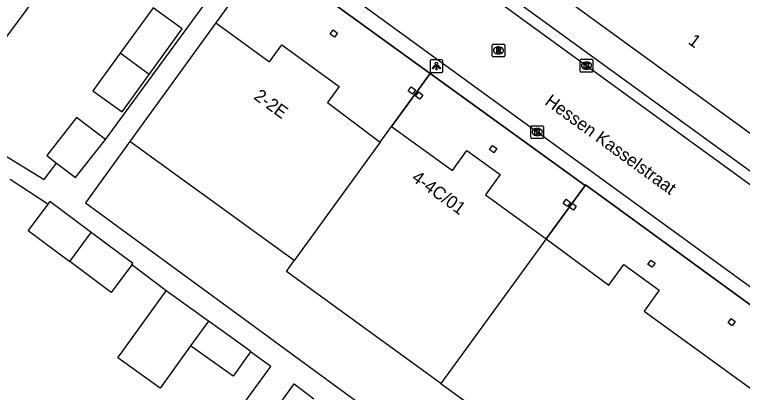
# Model space of a CAD drawing. Extents: x 160107 to 160928, y 382056 to 382918.
# Drawn here: x 160406.9 to 160464.1, y 382376.5 to 382406.2 of the extents above; entities that cross this region are included whole.
import ezdxf

# ---------------------------------------------------------------- set-up
doc = ezdxf.new("R2010")
doc.units = 0
for name, color, linetype in [('IMGEO_Kolk', 7, 'Continuous'), ('IMGEO_Lichtpunt', 7, 'Continuous'), ('IMGEO_Openbare_ruimte_label', 7, 'Continuous'), ('IMGEO_Pand', 7, 'Continuous'), ('IMGEO_Pand_nummerreeks', 7, 'Continuous'), ('IMGEO_Pand_overbouw', 7, 'Continuous'), ('IMGEO_Rijbaan_lokaal_open', 7, 'Continuous'), ('IMGEO_Rioolput', 7, 'Continuous'), ('IMGEO_Voetpad_open', 7, 'Continuous')]:
    doc.layers.add(name, color=color, linetype=linetype)

msp = doc.modelspace()

# ---------------------------------------------------------------- linework, layer by layer
at = {"layer": 'IMGEO_Kolk'}
for p, q in [((160451.322, 382401.736), (160451.322, 382402.588)), ((160451.397, 382402.662), (160452.249, 382402.662)), ((160451.81, 382402.442), (160451.835, 382402.442)), ((160452.323, 382402.588), (160452.323, 382401.736)), ((160451.833, 382401.882), (160451.808, 382401.882)), ((160452.249, 382401.662), (160451.397, 382401.662)), ((160447.445, 382396.513), (160447.445, 382397.365)), ((160447.52, 382397.439), (160448.372, 382397.439)), ((160447.933, 382397.219), (160447.958, 382397.219)), ((160448.446, 382397.365), (160448.446, 382396.513)), ((160447.956, 382396.659), (160447.931, 382396.659)), ((160448.372, 382396.439), (160447.52, 382396.439))]:
    msp.add_line(p, q, dxfattribs=at)
for points in [[(160451.322, 382401.736), (160451.322, 382402.588)], [(160451.397, 382402.662), (160452.249, 382402.662)], [(160451.643, 382402.362), (160451.766, 382402.362), (160451.766, 382402.211), (160451.896, 382402.362), (160452.06, 382402.362), (160451.914, 382402.211), (160452.067, 382401.962), (160451.915, 382401.962), (160451.83, 382402.126), (160451.766, 382402.059), (160451.766, 382401.962), (160451.643, 382401.962), (160451.643, 382402.362)], [(160452.323, 382402.588), (160452.323, 382401.736)], [(160452.249, 382401.662), (160451.397, 382401.662)], [(160447.445, 382396.513), (160447.445, 382397.365)], [(160447.52, 382397.439), (160448.372, 382397.439)], [(160448.446, 382397.365), (160448.446, 382396.513)], [(160447.766, 382397.139), (160447.889, 382397.139), (160447.889, 382396.988), (160448.019, 382397.139), (160448.183, 382397.139), (160448.037, 382396.988), (160448.19, 382396.739), (160448.038, 382396.739), (160447.953, 382396.903), (160447.889, 382396.836), (160447.889, 382396.739), (160447.766, 382396.739), (160447.766, 382397.139)], [(160448.372, 382396.439), (160447.52, 382396.439)]]:
    msp.add_lwpolyline(points, dxfattribs=at)
for centre, start, end in [((160451.399, 382402.586), 91.552, 178.448), ((160451.399, 382402.586), 91.552, 178.448), ((160452.247, 382402.586), 1.552, 88.448), ((160452.247, 382402.586), 1.552, 88.448), ((160451.399, 382401.738), 181.552, 268.448), ((160451.399, 382401.738), 181.552, 268.448), ((160452.247, 382401.738), 271.552, 358.448), ((160452.247, 382401.738), 271.552, 358.448), ((160447.522, 382397.363), 91.552, 178.448), ((160447.522, 382397.363), 91.552, 178.448), ((160448.37, 382397.363), 1.552, 88.448), ((160448.37, 382397.363), 1.552, 88.448), ((160447.522, 382396.515), 181.552, 268.448), ((160447.522, 382396.515), 181.552, 268.448), ((160448.37, 382396.515), 271.552, 358.448), ((160448.37, 382396.515), 271.552, 358.448)]:
    msp.add_arc(centre, 0.0765, start, end, dxfattribs=at)
for centre, major_axis, ratio, start_param, end_param in [((160451.809, 382402.162), (-0.387, 0.002), 0.722429, 4.712389, 7.853982), ((160451.834, 382402.162), (-0.39, 0.002), 0.717154, 1.570796, 4.712389), ((160447.932, 382396.939), (-0.387, 0.002), 0.722429, 4.712389, 7.853982), ((160447.957, 382396.939), (-0.39, 0.002), 0.717154, 1.570796, 4.712389)]:
    msp.add_ellipse(centre, major_axis=major_axis, ratio=ratio, start_param=start_param, end_param=end_param, dxfattribs=at)
at = {"layer": 'IMGEO_Lichtpunt'}
for p, q in [((160439.517, 382402.537), (160439.517, 382401.73)), ((160439.517, 382402.537), (160439.517, 382401.73)), ((160440.419, 382402.632), (160439.611, 382402.632)), ((160440.419, 382402.632), (160439.611, 382402.632)), ((160440.513, 382401.73), (160440.513, 382402.537)), ((160440.513, 382401.73), (160440.513, 382402.537)), ((160439.611, 382401.636), (160440.419, 382401.636)), ((160439.611, 382401.636), (160440.419, 382401.636))]:
    msp.add_line(p, q, dxfattribs=at)
for points in [[(160439.891, 382402.201), (160439.93, 382402.173), (160439.742, 382401.911), (160439.704, 382401.938), (160439.891, 382402.201)], [(160439.993, 382402.153), (160440.04, 382402.153), (160440.04, 382401.831), (160439.993, 382401.831), (160439.993, 382402.153)], [(160440.103, 382402.173), (160440.141, 382402.2), (160440.328, 382401.938), (160440.289, 382401.91), (160440.103, 382402.173)]]:
    msp.add_lwpolyline(points, dxfattribs=at)
msp.add_circle((160440.016, 382402.335), 0.0994, dxfattribs=at)
for centre, start, end in [((160439.611, 382402.537), 90, 180), ((160439.611, 382402.537), 90, 180), ((160440.419, 382402.537), 0, 90), ((160440.419, 382402.537), 0, 90), ((160439.611, 382401.73), 180, 270), ((160439.611, 382401.73), 180, 270), ((160440.419, 382401.73), 270, 0), ((160440.419, 382401.73), 270, 360)]:
    msp.add_arc(centre, 0.0946, start, end, dxfattribs=at)
at = {"layer": 'IMGEO_Pand'}
for points in [[(160496.01, 382423.19), (160472.739, 382390.992), (160443.139, 382412.509), (160443.937, 382413.611), (160446.425, 382417.048), (160445.872, 382417.448), (160446.399, 382418.176), (160446.953, 382417.775), (160449.135, 382420.786), (160468.398, 382406.625), (160478.135, 382420.019), (160485.824, 382430.595)], [(160407.012, 382409.239), (160408.78, 382407.934), (160405.026, 382402.846), (160403.258, 382404.151)], [(160417.428, 382401.465), (160420.031, 382405.061), (160417.747, 382406.714), (160415.168, 382403.151)], [(160422.678, 382405.539), (160415.913, 382396.21)], [(160422.678, 382405.539), (160426.902, 382402.469), (160427.869, 382403.803), (160432.376, 382400.519), (160431.463, 382399.257), (160435.599, 382396.137)], [(160432.001, 382404.403), (160431.668, 382404.65), (160431.909, 382404.97), (160432.241, 382404.723), (160432.001, 382404.403)], [(160415.168, 382403.151), (160413.017, 382400.18), (160415.301, 382398.527), (160417.428, 382401.465)], [(160417.428, 382401.465), (160415.168, 382403.151)], [(160438.144, 382399.928), (160437.809, 382400.172), (160438.046, 382400.494), (160438.383, 382400.254), (160438.144, 382399.928)], [(160438.721, 382399.517), (160438.379, 382399.769), (160438.626, 382400.094), (160438.961, 382399.849), (160438.721, 382399.517)], [(160413.99, 382396.362), (160411.724, 382398.098), (160409.383, 382395.092), (160410.161, 382394.496)], [(160435.599, 382396.137), (160436.5, 382397.379), (160441.294, 382393.92), (160442.415, 382395.503), (160445.027, 382393.592), (160443.871, 382392.002), (160448.643, 382388.532)], [(160410.161, 382394.496), (160411.65, 382393.356), (160413.99, 382396.362)], [(160428.847, 382386.83), (160415.913, 382396.21)], [(160435.599, 382396.137), (160428.847, 382386.83)], [(160444.525, 382395.318), (160444.188, 382395.56), (160444.425, 382395.886), (160444.761, 382395.641), (160444.525, 382395.318)], [(160412.884, 382389.036), (160409.619, 382391.476), (160409.471, 382391.278)], [(160449.995, 382391.327), (160450.23, 382391.653), (160450.566, 382391.409), (160450.328, 382391.08), (160449.995, 382391.327)], [(160409.471, 382391.278), (160407.922, 382389.206), (160411.187, 382386.765)], [(160450.785, 382390.791), (160450.459, 382391.022), (160450.691, 382391.351), (160451.018, 382391.12), (160450.785, 382390.791)], [(160411.187, 382386.765), (160412.884, 382389.036)], [(160416.073, 382386.493), (160416.149, 382386.595), (160412.884, 382389.036)], [(160448.643, 382388.532), (160440.354, 382377.176)], [(160448.643, 382388.532), (160453.568, 382384.905), (160454.761, 382386.535), (160457.54, 382384.501), (160456.351, 382382.868), (160466.187, 382375.719), (160467.365, 382377.35), (160470.157, 382375.333), (160468.968, 382373.7), (160478.776, 382366.565), (160479.978, 382368.175), (160482.771, 382366.161), (160481.591, 382364.526), (160491.395, 382357.376), (160492.59, 382358.99), (160495.379, 382356.975), (160494.187, 382355.357), (160499.315, 382351.619)], [(160416.073, 382386.493), (160414.452, 382384.325), (160411.187, 382386.765)], [(160440.354, 382377.176), (160428.236, 382385.988), (160428.847, 382386.83)], [(160456.977, 382386.304), (160456.652, 382386.537), (160456.888, 382386.865), (160457.212, 382386.632), (160456.977, 382386.304)], [(160420.696, 382380.133), (160418.302, 382376.803), (160414.982, 382379.19), (160418.775, 382384.467)], [(160422.096, 382382.08), (160418.775, 382384.467)], [(160422.096, 382382.08), (160420.696, 382380.133)], [(160425.404, 382379.653), (160425.427, 382379.685), (160422.448, 382381.827), (160422.096, 382382.08)], [(160463.191, 382382.273), (160463.516, 382382.04), (160463.282, 382381.713), (160462.957, 382381.946), (160463.191, 382382.273)], [(160425.404, 382379.653), (160424.028, 382377.738), (160420.696, 382380.133)], [(160440.354, 382377.176), (160491.079, 382340.291), (160491.222, 382340.488), (160491.833, 382341.328)]]:
    msp.add_lwpolyline(points, dxfattribs=at)
at = {"layer": 'IMGEO_Pand_overbouw'}
for points in [[(160435.599, 382396.137), (160436.5, 382397.379), (160439.531, 382401.558), (160426.593, 382410.937), (160422.678, 382405.539), (160426.902, 382402.469), (160427.869, 382403.803), (160432.376, 382400.519), (160431.463, 382399.257)], [(160439.531, 382401.558), (160436.5, 382397.379), (160441.294, 382393.92), (160442.415, 382395.503), (160445.027, 382393.592), (160443.871, 382392.002), (160448.643, 382388.532), (160451.707, 382392.731)], [(160451.707, 382392.731), (160448.643, 382388.532), (160453.568, 382384.905), (160454.761, 382386.535), (160457.54, 382384.501), (160456.351, 382382.868), (160466.187, 382375.719), (160467.365, 382377.35), (160470.157, 382375.333), (160468.968, 382373.7), (160478.776, 382366.565), (160479.978, 382368.175), (160482.771, 382366.161), (160481.591, 382364.526), (160491.395, 382357.376), (160492.59, 382358.99), (160495.379, 382356.975), (160494.187, 382355.357), (160499.315, 382351.619), (160502.419, 382355.889), (160498.105, 382359.029), (160451.741, 382392.778)]]:
    msp.add_lwpolyline(points, close=True, dxfattribs=at)
at = {"layer": 'IMGEO_Rijbaan_lokaal_open'}
for points in [[(160498.608, 382368.158), (160429.934, 382418.064), (160429.691, 382417.738), (160411.998, 382430.553)], [(160498.881, 382360.163), (160498.767, 382359.996), (160408.261, 382425.803)]]:
    msp.add_lwpolyline(points, dxfattribs=at)
at = {"layer": 'IMGEO_Rioolput'}
for p, q in [((160444.399, 382402.934), (160444.399, 382403.786)), ((160444.474, 382403.86), (160445.326, 382403.86)), ((160444.887, 382403.64), (160444.912, 382403.64)), ((160445.4, 382403.786), (160445.4, 382402.934)), ((160444.91, 382403.08), (160444.885, 382403.08)), ((160445.326, 382402.86), (160444.474, 382402.86))]:
    msp.add_line(p, q, dxfattribs=at)
for points in [[(160444.399, 382402.934), (160444.399, 382403.786)], [(160444.474, 382403.86), (160445.326, 382403.86)], [(160444.988, 382403.558), (160444.736, 382403.56), (160444.736, 382403.16)], [(160444.914, 382403.479), (160444.86, 382403.479), (160444.86, 382403.398)], [(160445.4, 382403.786), (160445.4, 382402.934)], [(160444.736, 382403.16), (160444.86, 382403.16), (160444.86, 382403.322), (160444.871, 382403.322)], [(160444.86, 382403.398), (160444.912, 382403.398)], [(160444.918, 382403.293), (160444.989, 382403.16), (160445.129, 382403.16), (160445.064, 382403.286)], [(160445.326, 382402.86), (160444.474, 382402.86)]]:
    msp.add_lwpolyline(points, dxfattribs=at)
for centre, radius, start, end in [((160444.476, 382403.784), 0.0765, 91.552, 178.448), ((160444.476, 382403.784), 0.0765, 91.552, 178.448), ((160444.92, 382403.383), 0.0964, 77.0061, 93.1865), ((160444.934, 382403.44), 0.0378, 276.6634, 79.6772), ((160444.987, 382403.448), 0.109, 350.3612, 89.416), ((160445.324, 382403.784), 0.0765, 1.552, 88.448), ((160445.324, 382403.784), 0.0765, 1.552, 88.448), ((160444.476, 382402.936), 0.0765, 181.552, 268.448), ((160444.476, 382402.936), 0.0765, 181.552, 268.448), ((160444.87, 382403.269), 0.0533, 26.0293, 88.6989), ((160444.896, 382403.587), 0.19, 274.7715, 282.9687), ((160444.985, 382403.448), 0.112, 277.5842, 350.9817), ((160444.969, 382403.233), 0.108, 29.5134, 73.7905), ((160445.324, 382402.936), 0.0765, 271.552, 358.448), ((160445.324, 382402.936), 0.0765, 271.552, 358.448)]:
    msp.add_arc(centre, radius, start, end, dxfattribs=at)
for centre, major_axis, ratio, start_param, end_param in [((160444.886, 382403.36), (-0.387, 0.002), 0.722429, 4.712389, 7.853982), ((160444.911, 382403.36), (-0.39, 0.002), 0.717154, 1.570796, 4.712389)]:
    msp.add_ellipse(centre, major_axis=major_axis, ratio=ratio, start_param=start_param, end_param=end_param, dxfattribs=at)
at = {"layer": 'IMGEO_Voetpad_open'}
for points in [[(160430.325, 382418.844), (160481.724, 382381.525), (160497.679, 382369.934)], [(160426.593, 382410.937), (160422.678, 382405.539)], [(160426.593, 382410.937), (160439.531, 382401.558), (160451.707, 382392.731), (160451.741, 382392.778), (160498.105, 382359.029), (160502.419, 382355.889), (160499.315, 382351.619)], [(160413.99, 382396.362), (160423.001, 382408.66)], [(160399.539, 382399.112), (160409.171, 382393.204), (160410.161, 382394.496)], [(160415.913, 382396.21), (160412.43, 382391.364), (160425.336, 382381.931), (160428.978, 382379.269), (160437.754, 382372.855), (160440.41, 382370.914)], [(160409.471, 382391.278), (160406.501, 382393.202)], [(160418.775, 382384.467), (160416.073, 382386.493)], [(160416.846, 382364.55), (160425.502, 382376.455), (160426.995, 382378.508), (160425.404, 382379.653)], [(160418.835, 382363.246), (160426.101, 382373.345), (160428.826, 382377.131), (160430.388, 382375.956)]]:
    msp.add_lwpolyline(points, dxfattribs=at)

# ---------------------------------------------------------------- texts
at = {"layer": 'IMGEO_Openbare_ruimte_label'}
msp.add_text('Hessen Kasselstraat', height=1, rotation=323.9895, dxfattribs=at).set_placement((160448.474, 382399.175))
at = {"layer": 'IMGEO_Pand_nummerreeks'}
for s, rotation, p in [('1', 324.0927, (160459.745, 382403.938)), ('2-2E', 323.9667, (160425.588, 382399.596)), ('4-4C/01', 323.9781, (160438.001, 382393.179))]:
    msp.add_text(s, height=1, rotation=rotation, dxfattribs=at).set_placement(p)

doc.saveas('drawing.dxf')
